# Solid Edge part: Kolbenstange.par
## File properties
Username: bmolnar
Dokumentum tartalom típus: 0
Author: bmolnar
Last saved by: bmolnar
Revision: 85
Sűrűség: 0,000 kg/m^3
Pontosság: 0,990
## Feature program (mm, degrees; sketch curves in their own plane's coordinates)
base feature "unnamed BaseFeature 1"
sketch for "unnamed Protrusion 1" plane through (34.5, 0, 0) normal (1, 0, 0) x-axis (0, 0, -1)
  circle centre (0, 0) radius 50
extrude "unnamed Protrusion 1" add finite 28 along +normal
sketch for "Furat_1" plane through (-45, 0, 0) normal (-1, 0, 0) x-axis (0, -1, 0)
hole "Furat_1" diameter 10 finite  VBottomAngle = 118 deg
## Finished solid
Body 1: solid body, 13 faces, 19 edges, 8 vertices.
  Faces by surface: plane 7, cylinder 3, cone 2, torus 1
  Edges by curve: circle 9, line 6, ellipse 2, intersection 2
Bounding box of the edges (mm; curved faces can reach further): 107.545 x 100.000 x 100.000, from (-45.0451, -50, -50) to (62.5, 50, 50).
Cylindrical faces by radius (mm): R5 x1, R12.5 x1, R50 x1
Conical faces (half-angle, radius in mm at the cone's reference point): 45 deg R5.553 x1, 59 deg R5 x1
Toroidal faces (ring radius, tube radius in mm): R10.7 r1.8 x1
Planar faces by outward normal: +x 1, +y 1, -x 2, -y 1, oblique 2
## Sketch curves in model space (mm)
circle centre (34.5, 0, 0) radius 50
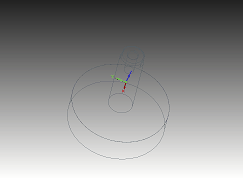
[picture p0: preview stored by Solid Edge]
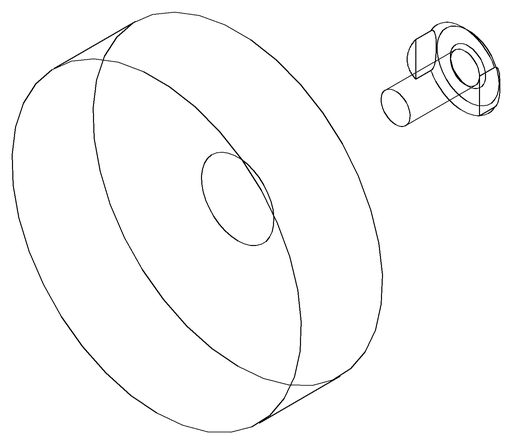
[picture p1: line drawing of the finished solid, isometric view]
